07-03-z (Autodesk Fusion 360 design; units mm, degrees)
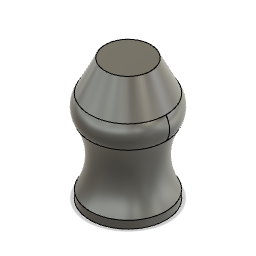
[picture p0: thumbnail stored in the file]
sketch "スケッチ1" plane through (0, 0, 0) normal (0, 1, 0) x axis (1, 0, 0)
  circle C1 centre (0, 0) radius 25
  point P1 (0, 0)
  point P2 (0, 0)
  coincident P1 P2
  dimension "d1" diameter C1 = 50
extrude "押し出し" new body sketch "スケッチ1" along normal blind 5
work_plane "作業平面1" AlongDistance 20
sketch "スケッチ2" plane through (0, 25, 0) normal (0, 1, 0) x axis (1, 0, 0)
  circle C1 centre (0, 0) radius 20
  point P1 (0, 0)
  point P2 (0, 0)
  coincident P1 P2
  dimension "d5" diameter C1 = 40
work_plane "作業平面2" AlongDistance 20
sketch "スケッチ3" plane through (0, 45, 0) normal (0, 1, 0) x axis (1, 0, 0)
  circle C1 centre (0, 0) radius 25
loft "ロフト1" sketch "スケッチ2" + "スケッチ3"
work_plane "作業平面3" AlongDistance 15
sketch "スケッチ4" plane through (0, 60, 0) normal (0, 1, 0) x axis (1, 0, 0)
  circle C1 centre (0, 0) radius 25
sketch "スケッチ5" plane through (0, 0, 0) normal (0, 0, 1) x axis (1, 0, 0)
  line L1 (-25, 60) -> (25, 60)
  line L2 (25, 45) -> (-25, 45)
  arc A1 centre (-14.3816, 52.5) radius 13 clockwise from (-25, 45) to (-25, 60)
  arc A2 centre (14.3816, 52.5) radius 13 clockwise from (25, 60) to (25, 45)
  point P2 (-25, 60)
  point P9 (-25, 60)
  point P3 (-25, 45)
  point P10 (-25, 45)
  point P5 (25, 60)
  point P8 (25, 60)
  point P6 (25, 45)
  point P11 (25, 45)
  coincident P2 P9
  coincident P3 P10
  coincident P5 P8
  coincident P6 P11
  equal A1 A2
  dimension "d8" radius A1 = 13
sketch "スケッチ6" plane through (0, 0, 0) normal (1, 0, 0) x axis (0, 0, -1)
  line L1 (-25, 60) -> (25, 60)
  line L2 (25, 45) -> (-25, 45)
  arc A1 centre (-14.3816, 52.5) radius 13 clockwise from (-25, 45) to (-25, 60)
  arc A2 centre (14.3816, 52.5) radius 13 clockwise from (25, 60) to (25, 45)
  point P2 (-25, 60)
  point P9 (-25, 60)
  point P3 (-25, 45)
  point P10 (-25, 45)
  point P6 (25, 45)
  point P11 (25, 45)
  point P5 (25, 60)
  point P8 (25, 60)
  coincident P2 P9
  coincident P3 P10
  coincident P6 P11
  coincident P5 P8
  equal A1 A2
  dimension "d9" radius A1 = 13
loft "ロフト2" sketch "スケッチ4"
work_plane "作業平面4" AlongDistance 20
sketch "スケッチ7" plane through (0, 80, 0) normal (0, 1, 0) x axis (1, 0, 0)
  circle C1 centre (0, 0) radius 15
  point P1 (0, 0)
  point P2 (0, 0)
  coincident P1 P2
  dimension "d12" diameter C1 = 30
loft "ロフト3" sketch "スケッチ7"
